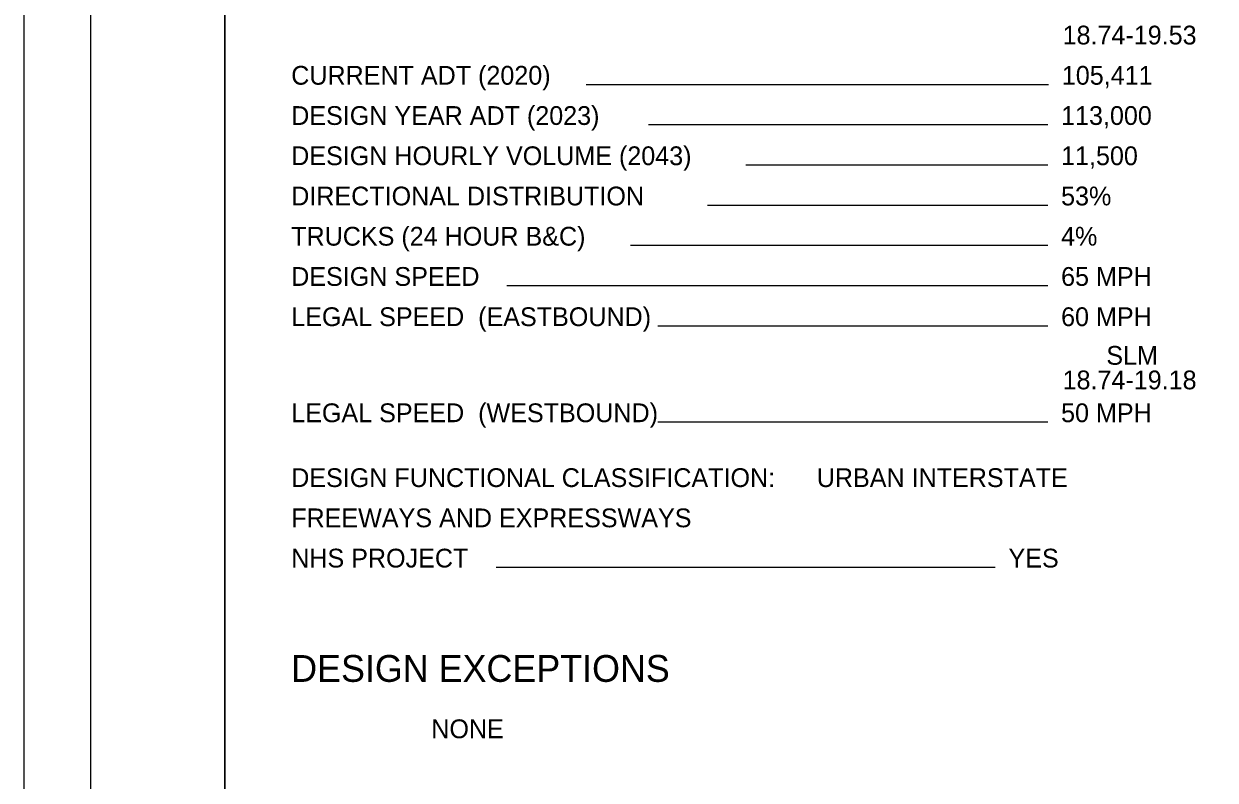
# Model space of a CAD drawing. Extents: x -17.5 to 72.9, y -57.8 to 32.3.
# Drawn here: x 0 to 8.89, y 5.64 to 11.28 of the extents above; entities that cross this region are included whole.
import ezdxf

# ---------------------------------------------------------------- set-up
doc = ezdxf.new("R2010")
doc.units = 0
for name, color, linetype in [('SH_Border', 7, 'Continuous'), ('SH_Cut_Line', 7, 'Continuous'), ('SH_Data', 7, 'Continuous'), ('SH_Text', 7, 'Continuous')]:
    doc.layers.add(name, color=color, linetype=linetype)

msp = doc.modelspace()

# ---------------------------------------------------------------- linework, layer by layer
at = {"layer": 'SH_Border'}
for points in [[(0.5, 21.5), (1.5, 21.5), (1.5, 0.5), (0.5, 0.5)], [(1.5, 21.5), (33.5, 21.5), (33.5, 0.5), (1.5, 0.5)]]:
    msp.add_lwpolyline(points, close=True, dxfattribs=at)
at = {"layer": 'SH_Cut_Line'}
msp.add_lwpolyline([(0, 0), (34, 0), (34, 22), (0, 22)], close=True, dxfattribs=at)
at = {"layer": 'SH_Data'}
for p, q in [((7.6424, 10.8271), (4.1936, 10.8271)), ((7.6368, 10.5271), (4.6592, 10.5271)), ((7.6368, 10.2271), (5.3852, 10.2271)), ((7.6368, 9.9271), (5.0988, 9.9271)), ((7.6368, 9.6271), (4.5259, 9.6271)), ((7.6368, 9.3271), (3.6035, 9.3271)), ((7.6368, 9.0271), (4.7298, 9.0271)), ((7.6368, 8.3107), (4.7298, 8.3107)), ((7.2445, 7.2271), (3.5243, 7.2271))]:
    msp.add_line(p, q, dxfattribs=at)

# ---------------------------------------------------------------- texts
for s, p in [('18.74-19.53', (7.748, 11.1271)), ('CURRENT ADT (2020)', (1.9944, 10.8271)), ('105,411', (7.7424, 10.8271)), ('DESIGN YEAR ADT (2023)', (1.9944, 10.5271)), ('113,000', (7.7368, 10.5271)), ('DESIGN HOURLY VOLUME (2043)', (1.9944, 10.2271)), ('11,500', (7.7368, 10.2271)), ('DIRECTIONAL DISTRIBUTION', (1.9944, 9.9271)), ('53%', (7.7368, 9.9271)), ('TRUCKS (24 HOUR B&C)', (1.9944, 9.6271)), ('4%', (7.7368, 9.6271)), ('DESIGN SPEED', (1.9944, 9.3271)), ('65 MPH', (7.7368, 9.3271)), ('LEGAL SPEED  (EASTBOUND)', (1.9944, 9.0271)), ('60 MPH', (7.7368, 9.0271)), ('SLM', (8.0741, 8.7388)), ('18.74-19.18', (7.748, 8.5558)), ('LEGAL SPEED  (WESTBOUND)', (1.9944, 8.3107)), ('50 MPH', (7.7368, 8.3107)), ('DESIGN FUNCTIONAL CLASSIFICATION:', (1.9944, 7.8271)), ('URBAN INTERSTATE', (5.9144, 7.8271)), ('FREEWAYS AND EXPRESSWAYS', (1.9944, 7.5271)), ('NHS PROJECT', (1.9944, 7.2271)), ('YES', (7.3445, 7.2271))]:
    msp.add_text(s, height=0.14, dxfattribs=at).set_placement(p)
at = {"layer": 'SH_Text'}
for s, height, p in [('DESIGN EXCEPTIONS', 0.2, (1.9944, 6.3744)), ('                  NONE                 ', 0.14, (2.103, 5.9544))]:
    msp.add_text(s, height=height, dxfattribs=at).set_placement(p)

doc.saveas('drawing.dxf')
